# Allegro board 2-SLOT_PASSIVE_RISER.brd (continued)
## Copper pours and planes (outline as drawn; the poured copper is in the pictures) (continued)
GND on IN2 (solid shape): 148,75.89 149.05,75.45 149.49,74.4 149.49,10.41 149.05,9.35 148,8.92 126.53,8.92 126.45,8.99 126.45,9.32 126.56,9.42 148,9.42 148.69,9.71 148.98,10.41 148.98,74.4 148.69,75.1 148,75.38 2,75.38 1.3,75.1 1.02,74.4 1.02,12 1.3,11.3 2,11.02 6.08,11.02 6.28,10.82 7.36,10.82 7.56,11.02 41.06,11.02 41.11,10.99 41.13,10.94 41.13,9.53 40.95,9.35 40.67,9.35 40.62,9.4 40.62,10.51 2,10.51 0.94,10.94 0.51,12 0.51,74.4 0.94,75.45 2,75.89
GND on GND1 (solid shape): outline of 8785 points within 0.51,5.66 149.49,75.89
P3V3_CLK_BUF_VDDA on TOP (solid shape): 95.64,27.86 95.64,27.23 95.59,27.18 94.98,27.18 94.63,27.53 92.42,27.53 92.3,27.66 91.53,27.66 91.45,27.74 91.45,28.73 91.64,28.92 94.59,28.92
P3V3_CLK_BUF_VDDIO on TOP (solid shape): 92.27,27.33 92.27,26.06 92.37,25.96 92.41,25.9 92.47,25.85 92.83,25.5 95.2,25.5 95.22,25.5 95.33,25.48 95.44,25.48 95.46,25.48 95.5,25.47 95.63,25.34 95.67,25.3 95.71,25.26 96.13,24.84 97.73,24.84 97.78,24.79 97.78,24.56 97.75,24.54 96.15,24.54 95.62,24 94.98,24 94.86,24.13 91.4,24.13 91.21,24.32 91.21,27.29 91.33,27.41 92.19,27.41
P3V3_CLK_BUF_VDDIO on BOTTOM (solid shape): outline of 146 points within 90.77,24.79 105.12,32.33
P3V3_SLOT1 on TOP (solid shape): 92.67,23.44 92.67,21.74 92.55,21.62 91.4,21.62 91.23,21.79 91.23,23.5 91.28,23.55 92.57,23.55
P3V3_SLOT1 on TOP (solid shape): outline of 302 points within 113.16,1.43 119.56,22.99
P3V3_SLOT1 on BOTTOM (solid shape): outline of 261 points within 90.95,21.11 109.67,29.82
P3V3_SLOT1 on BOTTOM (solid shape): 119.37,21.84 119.37,21.24 119.26,21.13 119.26,20.72 118.7,20.16 118.68,20.16 118.16,19.82 118.09,19.19 118.1,19.18 118.1,18.43 118.04,18.31 117.92,18.28 116.92,17.44 117.92,16.6 118.04,16.57 118.1,16.45 118.1,15.93 118.04,15.81 117.92,15.78 116.92,14.94 117.92,14.1 118.04,14.07 118.1,13.95 118.1,13.46 117.92,12.94 118.1,12.42 118.1,11.29 119.1,10.29 119.1,8.4 117.55,6.86 117.55,6.86 117.16,6.46 117.16,6.23 117.15,6.22 117.15,5.9 117.14,5.9 117.14,1.5 117.12,1.45 117.07,1.43 116.43,1.43 116.41,1.45 116.41,5.9 116.21,5.9 116.09,6.02 116.09,12.09 116.17,12.22 116.32,12.22 117.62,13.02 116.2,13.56 116.03,13.54 115.94,13.68 115.94,13.84 115.46,14.33 115.31,14.69 115.31,15.82 116.09,16.6 116.1,16.64 116.13,16.67 116.62,17.31 116.35,18.07 116.33,18.08 116.32,18.11 116.32,18.16 115.94,18.54 115.94,21.97 116.45,22.48 118.73,22.48
P3V3_SLOT1 on IN1 (solid shape): outline of 3136 points within 87.36,5.97 128.39,29.72
P3V3_SLOT2 on TOP (solid shape): 35.8,64.77 35.8,51.69 35.42,51.31 30.98,51.31 30.34,51.94 30.34,64.77 30.98,65.41 35.17,65.41
P3V3_SLOT2 on TOP (solid shape): outline of 208 points within 113.78,30.1 119.56,43.31
P3V3_SLOT2 on IN1 (solid shape): outline of 4612 points within 22.75,31.37 129.78,74.55
P3V3_STBY on BOTTOM (solid shape): 115.39,11.56 115.44,11.54 115.46,11.48 115.46,9.94 115.3,9.78 115.3,6.1 115.18,5.97 115.18,5.93 115.14,5.9 115.14,2.63 115.05,2.54 114.54,2.54 114.42,2.67 114.42,5.84 114.16,6.1 114.16,11.48 114.18,11.54 114.24,11.56
P3V3_STBY on BOTTOM (solid shape): outline of 3323 points within 112.79,18.67 148.63,48.13
P3V3_STBY on IN2 (solid shape): outline of 4707 points within 110.99,6.48 148.58,52.45
P12V_SLOT1 on TOP (solid shape): 128,22.48 128,16.51 127.5,16 123.05,16 122.8,15.75 122.8,14.73 122.54,14.48 121.27,14.48 120.89,14.86 120.89,18.03 121.78,18.92 121.78,22.35 121.91,22.48 123.81,22.48 124.07,22.73 124.07,22.86 124.19,22.99 127.5,22.99
P12V_SLOT1 on TOP (solid shape): 124.23,10.76 124.23,8.29 123.46,7.52 123.46,6.33 123.13,5.99 123.13,1.5 123.11,1.45 123.05,1.43 122.5,1.43 122.44,1.45 122.42,1.5 122.42,5.93 122.38,5.97 122.17,5.97 122.13,5.93 122.13,1.5 122.11,1.45 122.06,1.43 121.5,1.43 121.44,1.45 121.42,1.5 121.42,10.79 121.55,10.92 124.07,10.92
P12V_SLOT1 on BOTTOM (solid shape): outline of 175 points within 120.64,1.43 128,21.84
P12V_SLOT1 on IN1 (solid shape): outline of 225 points within 120.89,7.11 128.26,21.97
P12V_SLOT2 on TOP (solid shape): 29.58,62.36 29.58,52.07 29.2,51.69 27.55,51.69 27.42,51.82 27.42,61.09 27.17,61.34 27.17,62.23 27.55,62.61 29.33,62.61
P12V_SLOT2 on TOP (solid shape): 127.87,42.93 127.87,37.67 127.88,37.66 127.88,36.96 127.24,36.32 123.05,36.32 122.67,35.94 122.67,34.92 123.05,34.54 123.06,34.54 125.08,32.51 125.08,30.73 124.83,30.48 121.65,30.48 121.53,30.61 121.53,33.78 120.89,34.42 120.89,38.35 121.78,39.24 121.78,42.67 121.91,42.8 123.81,42.8 124.45,43.43 127.37,43.43
P12V_SLOT2 on BOTTOM (solid shape): 127.87,42.93 127.87,38.25 127.88,38.24 127.88,34.71 128,33.69 128,33.66 127.98,33.63 125.34,30.99 121.78,30.99 120.89,31.88 120.89,32.51 120.92,32.55 120.99,32.57 121.06,32.59 121.13,32.63 121.19,32.67 121.25,32.72 121.31,32.77 121.36,32.83 121.4,32.89 121.44,32.96 121.46,33.03 121.48,33.11 121.5,33.18 121.5,33.26 121.5,33.34 121.48,33.41 121.46,33.49 121.44,33.56 121.4,33.63 121.36,33.69 121.31,33.75 121.25,33.81 121.19,33.85 121.13,33.89 121.06,33.93 120.99,33.95 120.92,33.97 120.89,34.01 120.89,34.54 124.5,34.54 124.5,35.99 123.05,35.99 123.05,34.54 120.89,34.54 120.89,38.35 121.78,39.24 121.78,42.67 122.04,42.93 123.94,42.93 124.45,43.43 127.37,43.43
P12V_SLOT2 on IN2 (solid shape): outline of 6416 points within 21.48,20.32 131.18,74.55

Small or netless copper shapes (teardrops, artwork), in the pictures only: 60 on TOP

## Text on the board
Ref Des/Silkscreen Top: PWR_Conn | A | Sliver_2(P0 PCIe 3CD) | Sliver_1(P0 PCIe 3AB) | Riser Slot2(P0 PCIe 3ABCD) | Riser Slot1(P1 PCIe 1ABCD) | PCB-2RSMOXL6-P0 | REV:P0
User.19: FIGURE | SIZE | 10.0 | 22.0 | 24.0 | 28.0 | 41.0 | 44.0 | 95.0 | 119.0 | 138.0 | 158.0 | DRILL CHART: TOP to BOTTOM | ALL UNITS ARE IN MILS | TOLERANCE | +3.0/-3.0 | +2.0/-2.0 | PLATED | NON-PLATED | QTY | 511 | 53 | 23 | 4 | 328 | 1 | 3
